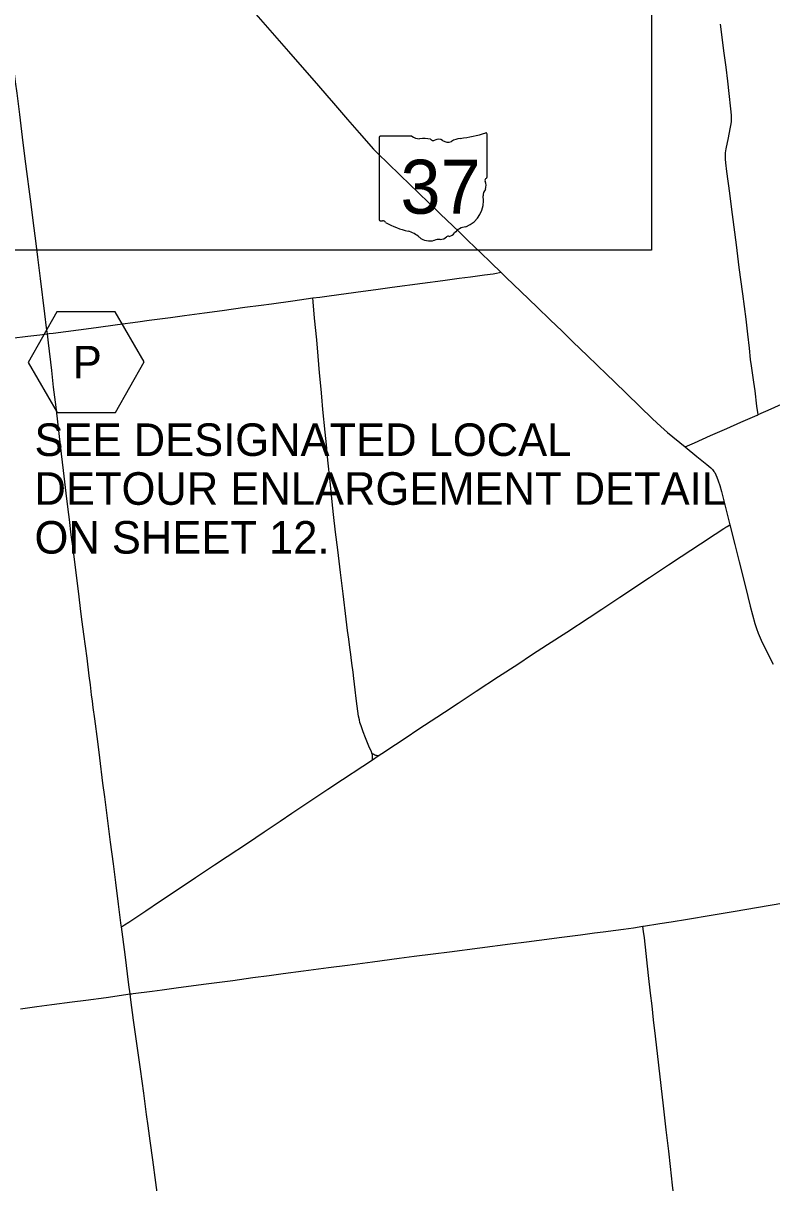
# Model space of a CAD drawing. Extents: x 0 to 680, y 0 to 440.
# Drawn here: x 72.2 to 136.6, y 233.7 to 333.5 of the extents above; entities that cross this region are included whole.
import ezdxf

# ---------------------------------------------------------------- set-up
doc = ezdxf.new("R2010")
doc.units = 0
for name, color, linetype in [('GM_X_County_Road', 7, 'Continuous'), ('GM_X_State_Route', 7, 'Continuous'), ('GM_X_State_Shield', 7, 'Continuous'), ('GM_X_Township_Road', 7, 'Continuous'), ('SH_Text', 7, 'Continuous')]:
    doc.layers.add(name, color=color, linetype=linetype)

msp = doc.modelspace()

# ---------------------------------------------------------------- linework, layer by layer
at = {"layer": 'GM_X_County_Road'}
for points in [[(74.29, 306.765), (74.225, 307.284), (74.08, 308.478), (73.698, 311.516), (73.469, 313.36), (73.292, 314.771), (73.098, 316.289), (72.891, 317.916), (72.718, 319.217), (72.585, 320.302), (72.387, 321.82), (72.152, 323.664), (71.91, 325.617), (71.678, 327.461), (71.554, 328.437), (71.345, 330.064), (71.196, 331.258), (71.054, 332.342), (70.97, 332.992), (70.807, 334.293)], [(71.214, 306.388), (72.6, 306.555), (73.641, 306.68), (74.29, 306.765)], [(80.654, 255.751), (80.64, 255.857), (80.404, 257.7), (80.179, 259.546), (79.969, 261.172), (79.73, 263.016), (79.224, 266.919), (79.07, 268.112), (78.794, 270.281), (78.617, 271.691), (78.368, 273.644), (78.242, 274.603), (78.168, 275.169), (78.098, 275.704), (77.986, 276.571), (77.892, 277.33), (77.7, 278.849), (77.434, 280.909), (77.292, 281.994), (77.175, 282.86), (76.989, 284.38), (76.677, 286.875), (76.494, 288.285), (76.339, 289.478), (76.179, 290.78), (76.074, 291.648), (75.908, 293.059), (75.674, 295.014), (75.508, 296.425), (75.22, 298.923), (75.043, 300.444), (74.826, 302.18), (74.663, 303.592), (74.39, 305.982), (74.29, 306.765)], [(135.444, 299.807), (136.557, 300.312), (138.649, 301.261)], [(129.176, 297.028), (129.363, 297.111), (129.961, 297.377), (131.361, 297.999), (132.76, 298.621), (133.957, 299.16), (135.361, 299.769), (135.444, 299.807)], [(81.412, 249.976), (81.308, 250.761), (80.968, 253.363), (80.654, 255.751)], [(71.967, 248.699), (73.378, 248.888), (74.679, 249.066), (76.414, 249.296), (77.608, 249.448), (79.343, 249.677), (81.412, 249.976)], [(85.079, 223.044), (84.959, 223.892), (84.589, 226.711), (84.33, 228.552), (84.143, 229.961), (83.884, 231.802), (83.734, 232.884), (83.618, 233.751), (83.353, 235.701), (83.134, 237.326), (82.961, 238.627), (82.826, 239.602), (82.576, 241.444), (82.289, 243.501), (81.712, 247.726), (81.481, 249.461), (81.412, 249.976)]]:
    msp.add_lwpolyline(points, dxfattribs=at)
at = {"layer": 'GM_X_State_Route'}
msp.add_lwpolyline([(92.225, 334.268), (93.227, 333.11), (95.029, 331.052), (97.614, 328.082), (98.326, 327.252), (98.895, 326.587), (100.119, 325.187), (101.128, 324.035), (102.363, 322.643), (102.821, 322.171), (103.527, 321.485), (104.705, 320.342), (105.414, 319.659), (107.073, 318.07), (108.096, 317.082), (109.754, 315.492), (110.538, 314.73), (111.489, 313.824), (112.509, 312.834), (113.304, 312.065), (113.768, 311.617), (115.032, 310.407), (116.447, 309.039), (117.552, 307.977), (118.575, 306.991), (119.507, 306.066), (120.138, 305.46), (120.768, 304.853), (122.422, 303.263), (123.047, 302.653), (124.145, 301.585), (126.346, 299.455), (127.063, 298.779), (127.645, 298.28), (129.176, 297.028), (130.186, 296.202), (131.037, 295.514), (131.364, 295.229), (131.514, 295.074), (131.648, 294.906), (131.707, 294.816), (131.812, 294.628), (131.904, 294.432), (132.02, 294.127), (132.154, 293.712), (132.298, 293.185), (132.64, 291.805), (133.013, 290.316), (133.452, 288.625), (133.821, 287.139), (134.251, 285.442), (134.559, 284.167), (134.771, 283.317), (135.169, 281.837), (135.3, 281.418), (135.452, 281.007), (135.621, 280.602), (135.807, 280.204), (136.75, 278.351)], dxfattribs=at)
msp.add_lwpolyline([(80.11, 308.66), (75.11, 308.644), (72.623, 304.306), (75.137, 299.984), (80.137, 300), (82.623, 304.338)], close=True, dxfattribs=at)
at = {"layer": 'GM_X_State_Shield'}
for p, q in [((102.84, 323.641), (102.84, 316.597)), ((105.649, 323.762), (102.931, 323.762)), ((112.121, 320.252), (112.121, 323.937)), ((112.12, 320.253), (112.121, 320.252))]:
    msp.add_line(p, q, dxfattribs=at)
for centre, radius, start, end in [((102.946, 323.656), 0.108, 98.1301, 188.1301), ((106.296, 324.58), 1.043, 231.61951, 271.11188), ((106.642, 319.808), 3.744, 80.48669, 94.98827), ((107.492, 323.693), 0.301, 219.79206, 297.10237), ((107.934, 322.878), 0.626, 54.46668, 119.14113), ((108.741, 323.995), 0.753, 233.85621, 294.82819), ((110.07, 321.611), 1.98, 97.34618, 120.76885), ((108.815, 333.366), 9.842, 275.84447, 288.90645), ((112.018, 323.952), 0.103, 351.86209, 97.738), ((112.011, 320.238), 0.111, 289.60381, 7.73413), ((112.097, 319.981), 0.16, 107.94398, 210.33697), ((111.08, 319.516), 0.96, 340.03296, 23.64957), ((109.366, 318.241), 2.462, 292.30889, 8.98584), ((112.491, 318.71), 0.698, 136.8065, 186.92959), ((102.947, 316.581), 0.108, 171.95839, 258.30661), ((102.963, 317.302), 0.828, 267.33899, 280.60386), ((103.133, 316.191), 0.298, 29.74838, 93.27175), ((106.901, 322.519), 7.108, 240.41292, 257.1985), ((104.782, 313.432), 2.224, 47.18416, 75.83597), ((108.696, 315.914), 0.795, 282.87319, 323.27711), ((110.404, 314.619), 1.348, 94.40312, 142.57675), ((107.188, 316.156), 1.411, 230.70037, 286.29184), ((108.003, 313.72), 1.16, 85.69512, 111.20995), ((108.106, 315.628), 0.752, 268.77702, 315.54927), ((108.786, 314.946), 0.212, 65.75173, 132.64842)]:
    msp.add_arc(centre, radius, start, end, dxfattribs=at)
at = {"layer": 'GM_X_Township_Road'}
msp.add_line((102.25, 270.108), (102.757, 270.448), dxfattribs=at)
for points in [[(135.444, 299.807), (135.418, 299.998), (135.345, 300.539), (135.185, 301.841), (135.081, 302.6), (134.869, 304.005), (134.799, 304.547), (134.699, 305.526), (134.566, 306.721), (134.408, 308.023), (134.122, 310.191), (133.827, 312.468), (133.58, 314.421), (133.388, 315.939), (133.167, 317.674), (133.018, 318.868), (132.762, 320.709), (132.671, 321.469), (132.643, 321.796), (132.634, 322.124), (132.645, 322.342), (132.692, 322.666), (132.896, 323.629), (133.049, 324.379), (133.125, 324.81), (133.15, 325.027), (133.16, 325.245), (133.152, 325.573), (133.104, 326.117), (132.956, 327.421), (132.83, 328.507), (132.686, 329.701), (132.499, 331.109), (132.265, 332.954), (132.216, 333.388)], [(97.133, 309.844), (97.736, 309.924), (98.543, 310.03), (101.47, 310.436), (102.554, 310.583), (103.965, 310.768), (106.568, 311.12), (108.303, 311.351), (109.713, 311.536), (110.69, 311.664), (111.889, 311.822), (112.643, 311.922), (112.927, 311.978), (113.187, 312.038), (113.304, 312.065)], [(74.29, 306.765), (74.437, 306.783), (74.791, 306.828), (75.876, 306.97), (76.961, 307.115), (78.48, 307.314), (80.325, 307.558), (82.06, 307.79), (83.036, 307.921), (84.88, 308.17), (86.077, 308.334), (87.808, 308.564), (89.332, 308.773), (91.281, 309.039), (92.688, 309.224), (93.559, 309.346), (95.407, 309.596), (97.133, 309.844)], [(100.351, 279.539), (100.223, 280.482), (100.122, 281.241), (100.004, 282.217), (99.739, 284.388), (99.507, 286.233), (99.272, 288.187), (99.092, 289.707), (98.911, 291.227), (98.791, 292.314), (98.609, 294.054), (98.421, 295.903), (98.293, 297.209), (98.187, 298.297), (98.003, 300.256), (97.905, 301.345), (97.844, 301.998), (97.714, 303.413), (97.584, 304.829), (97.46, 306.245), (97.281, 308.095), (97.161, 309.511), (97.133, 309.844)], [(102.757, 270.448), (103.063, 270.652), (104.245, 271.443), (105.068, 271.983), (106.256, 272.765), (107.809, 273.787), (108.449, 274.21), (109.635, 274.994), (111.192, 276.011), (113.109, 277.279), (114.757, 278.356), (115.949, 279.132), (117.324, 280.028), (118.973, 281.105), (120.896, 282.363), (121.995, 283.081), (123.548, 284.103), (126.103, 285.794), (127.744, 286.883), (128.838, 287.61), (130.483, 288.692), (131.762, 289.536), (132.491, 290.02), (132.676, 290.135), (132.773, 290.187), (133.013, 290.316)], [(102.216, 270.673), (102.201, 270.718), (102.169, 270.787), (101.952, 271.287), (101.659, 271.996), (101.465, 272.507), (101.283, 273.023), (101.186, 273.336), (101.131, 273.548), (101.065, 273.869), (100.996, 274.301), (100.941, 274.735), (100.866, 275.386), (100.779, 276.146), (100.662, 277.123), (100.597, 277.665), (100.498, 278.424), (100.37, 279.399), (100.351, 279.539)], [(102.25, 270.108), (102.258, 270.18), (102.27, 270.289), (102.278, 270.371), (102.275, 270.463), (102.27, 270.502), (102.258, 270.549), (102.216, 270.673)], [(102.757, 270.448), (102.694, 270.46), (102.62, 270.475), (102.557, 270.493), (102.466, 270.525), (102.391, 270.56), (102.337, 270.594), (102.272, 270.636), (102.216, 270.673)], [(80.654, 255.751), (80.932, 255.92), (81.305, 256.149), (82.758, 257.125), (83.941, 257.914), (85.035, 258.64), (87.032, 259.984), (88.674, 261.071), (89.769, 261.796), (91.497, 262.951), (92.949, 263.929), (94.316, 264.837), (95.314, 265.51), (96.859, 266.546), (98.407, 267.576), (99.685, 268.422), (101.426, 269.557), (102.25, 270.108)], [(125.519, 255.793), (125.588, 255.798), (126.992, 256.019), (127.963, 256.179), (129.366, 256.411), (131.415, 256.755), (133.464, 257.102), (135.297, 257.411), (137.672, 257.8), (139.183, 258.045), (140.37, 258.242), (141.88, 258.499), (143.714, 258.799), (145.658, 259.114), (146.089, 259.188), (146.379, 259.238)], [(81.412, 249.976), (81.568, 249.995), (81.677, 250.009), (83.304, 250.215), (84.171, 250.334), (85.58, 250.523), (87.965, 250.839), (90.242, 251.143), (91.976, 251.374), (93.385, 251.563), (94.578, 251.724), (96.313, 251.95), (97.179, 252.072), (98.479, 252.252), (100.106, 252.46), (102.275, 252.743), (104.552, 253.042), (105.853, 253.218), (107.48, 253.429), (108.891, 253.606), (111.493, 253.949), (114.097, 254.281), (115.508, 254.456), (116.591, 254.607), (118.543, 254.861), (120.17, 255.072), (121.362, 255.235), (122.122, 255.329), (123.206, 255.466), (123.856, 255.555), (124.724, 255.67), (125.519, 255.793)], [(128.614, 228.813), (128.583, 229.163), (128.529, 229.707), (128.305, 231.663), (128.089, 233.51), (127.898, 235.139), (127.754, 236.444), (127.547, 238.292), (127.311, 240.356), (126.906, 243.833), (126.623, 246.333), (126.456, 247.745), (126.322, 248.94), (126.197, 250.027), (126.015, 251.547), (125.658, 254.81), (125.592, 255.347), (125.562, 255.558), (125.519, 255.793)]]:
    msp.add_lwpolyline(points, dxfattribs=at)
at = {"layer": 'SH_Text'}
msp.add_lwpolyline([(48.072, 395.938), (126.265, 395.938), (126.265, 313.95), (48.072, 313.95)], close=True, dxfattribs=at)

# ---------------------------------------------------------------- texts
at = {"layer": 'GM_X_State_Route'}
msp.add_text('P', height=2.8, dxfattribs=at).set_placement((76.477, 302.922))
at = {"layer": 'GM_X_State_Shield'}
msp.add_text('37', height=4.6406, dxfattribs=at).set_placement((104.669, 317.094))
at = {"layer": 'SH_Text'}
for s, p in [('SEE DESIGNATED LOCAL', (73.182, 296.252)), ('DETOUR ENLARGEMENT DETAIL', (73.182, 292.052)), ('ON SHEET 12.', (73.182, 287.852))]:
    msp.add_text(s, height=2.8, dxfattribs=at).set_placement(p)

doc.saveas('drawing.dxf')
